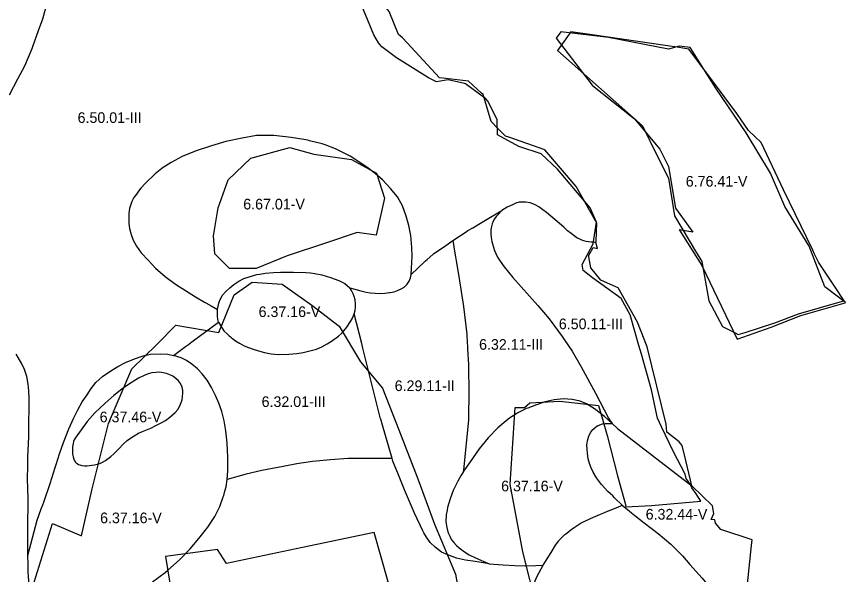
# Model space of a CAD drawing. Extents: x -555156 to -540209, y -1046851 to -1035695.
# Drawn here: x -542138 to -541359, y -1040907 to -1040382 of the extents above; entities that cross this region are included whole.
import ezdxf

# ---------------------------------------------------------------- set-up
doc = ezdxf.new("R2010")
doc.units = 0
for name, color, linetype in [('Vrstva 27', 7, 'Continuous'), ('Vrstva 28', 7, 'Continuous'), ('Vrstva 29', 7, 'Continuous')]:
    doc.layers.add(name, color=color, linetype=linetype)

msp = doc.modelspace()

# ---------------------------------------------------------------- linework, layer by layer
at = {"layer": 'Vrstva 28'}
for points in [[(-541593.76, -1040594.63), (-541593.48, -1040594.1), (-541593.07, -1040584.45), (-541592.73, -1040576.39), (-541600.47, -1040562.6), (-541602.39, -1040559.17), (-541612.08, -1040541.89), (-541641.71, -1040507.59), (-541675.45, -1040495.58), (-541678.57, -1040494.47), (-541685.72, -1040487.24), (-541692.18, -1040480.72), (-541699.7, -1040455.36), (-541701.04, -1040454.15), (-541713.43, -1040442.93), (-541734.8, -1040440.48), (-541740.52, -1040439.82), (-541770.98, -1040406.91), (-541775.35, -1040402.19), (-541779.11, -1040398.91), (-541788.04, -1040377.21), (-541798.74, -1040363.44)], [(-542144.84, -1040455.59), (-542137.07, -1040440.65), (-542130.51, -1040428.38), (-542123.64, -1040412.09), (-542122.95, -1040410.2), (-542117.51, -1040395.2), (-542113.48, -1040384.15), (-542109.84, -1040370.36)], [(-541453.1, -1040679.19), (-541425.36, -1040670.13), (-541403.1, -1040661.75), (-541361.89, -1040649.89), (-541360.03, -1040649.35), (-541369.26, -1040635.59), (-541384.41, -1040612.99), (-541387.93, -1040605.65), (-541389.7, -1040601.96), (-541417.07, -1040544.93), (-541438.36, -1040500.57), (-541450.27, -1040489.17), (-541460.97, -1040473.29), (-541495.79, -1040426.52), (-541506.12, -1040412.64), (-541509.91, -1040412.09), (-541517.03, -1040411.05), (-541526.16, -1040409.72), (-541597.19, -1040399.34), (-541617.11, -1040396.43), (-541629.8, -1040414.09), (-541549.65, -1040484.93), (-541535.57, -1040513.88), (-541525.44, -1040534.19), (-541519.72, -1040569.58)], [(-541766.63, -1040613.12), (-541766.57, -1040611.85), (-541766.45, -1040609.32), (-541766.48, -1040607.52), (-541766.6, -1040599.3), (-541767.49, -1040588.09), (-541769.44, -1040578.68), (-541771.98, -1040569.71), (-541775.56, -1040560.15), (-541780.19, -1040551.78), (-541786.61, -1040543.71), (-541794.08, -1040535.64), (-541801.25, -1040529.66), (-541808.87, -1040523.72), (-541824.7, -1040513.26), (-541838.29, -1040506.38), (-541848.26, -1040502.74), (-541850.99, -1040501.75), (-541862.76, -1040498.84), (-541864.28, -1040498.46), (-541868.25, -1040497.79), (-541880.12, -1040495.77), (-541896.25, -1040493.98), (-541912.68, -1040494.13), (-541926.12, -1040496.37), (-541941.66, -1040499.66), (-541955.1, -1040503.84), (-541969.44, -1040508.47), (-541982.73, -1040513.85), (-541992.89, -1040519.38), (-542001.26, -1040524.78), (-542001.7, -1040525.06), (-542007.98, -1040530.14), (-542017.09, -1040538.81), (-542021.33, -1040543.48), (-542023.55, -1040546.21), (-542025.6, -1040549.03), (-542027.99, -1040552.36), (-542029.86, -1040556.04), (-542031.23, -1040559.71), (-542032, -1040562.7), (-542032.77, -1040566.88), (-542032.77, -1040571.24), (-542032.59, -1040576.62), (-542032, -1040581.31), (-542030.55, -1040587.12), (-542028.75, -1040592.42), (-542025.43, -1040597.97), (-542021.09, -1040604.36), (-542014.69, -1040611.28), (-542007.52, -1040618.88), (-541998.65, -1040626.48), (-541988.74, -1040633.74), (-541969.91, -1040645.79), (-541961.55, -1040650.87), (-541960.42, -1040651.5), (-541955.36, -1040654.31), (-541949.45, -1040657.6)], [(-541593.76, -1040594.63), (-541594.82, -1040594.55), (-541596.25, -1040594.44), (-541598.14, -1040594.22), (-541600.76, -1040593.88), (-541602.63, -1040593.55), (-541604.78, -1040592.99), (-541606.78, -1040592.35), (-541608.79, -1040591.51), (-541610.86, -1040590.55), (-541612.59, -1040589.49), (-541614.48, -1040588.13), (-541616.97, -1040586.13), (-541620.19, -1040583.5), (-541623.75, -1040580.32), (-541631.88, -1040573.31), (-541640.05, -1040566.5), (-541643.55, -1040563.77), (-541647.14, -1040561.2), (-541650.55, -1040559.32), (-541653.03, -1040558.21), (-541655.5, -1040557.36), (-541659.34, -1040556.68), (-541662.67, -1040556.59), (-541665.83, -1040556.76), (-541668.82, -1040557.62), (-541672.15, -1040559.07), (-541677.03, -1040561.48), (-541682.16, -1040564.5)], [(-541728.16, -1040592.75), (-541715.69, -1040584.6), (-541713.97, -1040583.48), (-541709.32, -1040580.69), (-541700.53, -1040575.41), (-541690.97, -1040569.73), (-541682.16, -1040564.5)], [(-541682.16, -1040564.5), (-541685.9, -1040568.45), (-541687.51, -1040570.26), (-541688.92, -1040572.31), (-541690.24, -1040574.5), (-541691.26, -1040576.99), (-541691.9, -1040579.43), (-541692.29, -1040582.8), (-541692.29, -1040586.36), (-541692.09, -1040589.83), (-541691.46, -1040593.53), (-541689.14, -1040601.35), (-541688.83, -1040602.05), (-541687.57, -1040604.88), (-541686.01, -1040608.38), (-541683.47, -1040612.07), (-541679.73, -1040617.5), (-541671.82, -1040627.51), (-541648.09, -1040653.81), (-541637.38, -1040666.37), (-541628.67, -1040678.22), (-541627.97, -1040679.18), (-541626.05, -1040681.98), (-541623.49, -1040685.7), (-541615.94, -1040696.7), (-541607.58, -1040711.61), (-541593.99, -1040736.46)], [(-541519.72, -1040569.58), (-541498.86, -1040604.18), (-541496.75, -1040607.69), (-541493.95, -1040612.33), (-541487.3, -1040649.38), (-541474.46, -1040673.56), (-541462.77, -1040679.71), (-541459.84, -1040681.25), (-541453.1, -1040679.19)], [(-541767.2, -1040624.86), (-541754.75, -1040612.75), (-541753.86, -1040611.88), (-541752.24, -1040610.48), (-541746.99, -1040605.91), (-541745.94, -1040605), (-541736.83, -1040599.02), (-541728.16, -1040592.75)], [(-541728.16, -1040592.75), (-541726.15, -1040604.58), (-541725.56, -1040608.08), (-541724.92, -1040611.82), (-541722.39, -1040626.7)], [(-541503.49, -1040823.59), (-541504.79, -1040818.07), (-541509.15, -1040799.56), (-541512.44, -1040785.61), (-541513.95, -1040783.61), (-541515.19, -1040781.97), (-541527.02, -1040773.11), (-541527.61, -1040765.52), (-541545.26, -1040692.82), (-541546.61, -1040689.46), (-541548.24, -1040685.4), (-541554.63, -1040669.51), (-541572.61, -1040637.27), (-541574.2, -1040636.57), (-541588.99, -1040630.06), (-541598.3, -1040618.46), (-541600.29, -1040608.13), (-541600.45, -1040607.31), (-541596.27, -1040599.38), (-541592.01, -1040600.3), (-541593.76, -1040594.63)], [(-541767.2, -1040624.86), (-541766.63, -1040613.12)], [(-541949.45, -1040657.6), (-541948.24, -1040651.73), (-541947.9, -1040650.84), (-541946.87, -1040648.14), (-541945.41, -1040645.51), (-541944.83, -1040644.47), (-541941.67, -1040640.62), (-541937.91, -1040637.12), (-541933.9, -1040634.05), (-541929.21, -1040630.89), (-541924.68, -1040628.5), (-541919.73, -1040626.79), (-541912.31, -1040624.74), (-541909.49, -1040624.3), (-541904.62, -1040623.54), (-541896.69, -1040622.78), (-541890.2, -1040622.62), (-541886.44, -1040622.52), (-541878, -1040622.43), (-541877.82, -1040622.43), (-541866.21, -1040622.69), (-541861.9, -1040623.21), (-541857.76, -1040623.71), (-541851.19, -1040624.91), (-541843, -1040627.39), (-541835.15, -1040630.46), (-541829.78, -1040633.27), (-541827.05, -1040635.27), (-541825, -1040637.13)], [(-541825, -1040637.13), (-541820.27, -1040638.56), (-541814.55, -1040640.18), (-541809.6, -1040641.29), (-541805.59, -1040641.98), (-541801.24, -1040642.4), (-541796.46, -1040642.58), (-541792.1, -1040642.4), (-541787.57, -1040641.79), (-541787.07, -1040641.72), (-541783.23, -1040640.87), (-541779.98, -1040639.67), (-541776.83, -1040638.31), (-541773.75, -1040636.51), (-541771.11, -1040633.69), (-541769.77, -1040631.81), (-541769.23, -1040631.05), (-541768.03, -1040627.8), (-541767.2, -1040624.86)], [(-541722.39, -1040626.7), (-541717.94, -1040654.68), (-541715.07, -1040680.84), (-541714.63, -1040688.92), (-541714.45, -1040692.15), (-541714.29, -1040695.02), (-541713.5, -1040709.35), (-541712.98, -1040737.59), (-541713.41, -1040757.44), (-541713.5, -1040761.65), (-541718.21, -1040808.41), (-541718.44, -1040810.69)], [(-541820.72, -1040661.8), (-541820.04, -1040658.72), (-541819.65, -1040655.4), (-541819.5, -1040652.28), (-541819.88, -1040648.65), (-541820.71, -1040645.52), (-541821.73, -1040642.74), (-541823.25, -1040639.81), (-541825, -1040637.13)], [(-541948.34, -1040669.66), (-541948.98, -1040667.13), (-541949.37, -1040663.81), (-541949.46, -1040660), (-541949.45, -1040657.6)], [(-541882.19, -1040699.74), (-541874.76, -1040698.97), (-541868.7, -1040698.03), (-541862.56, -1040696.49), (-541856.41, -1040694.87), (-541851.12, -1040692.65), (-541846.25, -1040690), (-541843.68, -1040688.32), (-541841.37, -1040686.81), (-541839.85, -1040685.82), (-541835.58, -1040682.57), (-541832.26, -1040679.5), (-541827.82, -1040674.29), (-541824.38, -1040669.07), (-541822.43, -1040665.65), (-541820.72, -1040661.8)], [(-541812.67, -1040693.87), (-541813.38, -1040691.02), (-541814.07, -1040688.27), (-541820.72, -1040661.8)], [(-541990.68, -1040700.75), (-541979.31, -1040692.4), (-541976.74, -1040690.51), (-541973.51, -1040688.14), (-541948.34, -1040669.66)], [(-541948.34, -1040669.66), (-541946.68, -1040672.59), (-541945.07, -1040675.23), (-541943.26, -1040677.73), (-541940.1, -1040680.8), (-541938.76, -1040681.94), (-541937.02, -1040683.41), (-541936.17, -1040684.13), (-541935.28, -1040684.8), (-541932.42, -1040686.95), (-541928.66, -1040689.43), (-541924.14, -1040691.65), (-541920.21, -1040693.36), (-541915.77, -1040694.98), (-541910.91, -1040696.6), (-541905.11, -1040698.14), (-541898.96, -1040699.33), (-541891.88, -1040699.85), (-541882.19, -1040699.74)], [(-542127.79, -1040889.01), (-542127.64, -1040859.67), (-542127.38, -1040840.58), (-542127.39, -1040839.99), (-542127.49, -1040835.62), (-542127.9, -1040816.51), (-542127.75, -1040805.18), (-542127.64, -1040796.64), (-542126.85, -1040777.28), (-542126.59, -1040758.93), (-542126.55, -1040755.77), (-542126.51, -1040753.28), (-542126.49, -1040751.78), (-542126.49, -1040741.32), (-542126.64, -1040734.15), (-542127.39, -1040727.72), (-542128.73, -1040720.7), (-542130.82, -1040714.12), (-542133.66, -1040708), (-542138.74, -1040699.7)], [(-542127.79, -1040889.01), (-542119.02, -1040855.8), (-542115.09, -1040845.12), (-542113.68, -1040841.28), (-542112.75, -1040838.77), (-542106.62, -1040821.43), (-542101.99, -1040806.34), (-542101.04, -1040803.4), (-542097.81, -1040793.33), (-542094.08, -1040782.72), (-542089.18, -1040769.87), (-542084.55, -1040759.41), (-542080.52, -1040752.09), (-542076.49, -1040744.61), (-542072.01, -1040737.74), (-542068.12, -1040731.91), (-542063.64, -1040726.38), (-542057.52, -1040720.7), (-542049.6, -1040715.17), (-542043.03, -1040711.14), (-542035.71, -1040707.55), (-542027.35, -1040703.96), (-542019.13, -1040701.27), (-542012.41, -1040699.78), (-542002.77, -1040699.4), (-541996.05, -1040699.7), (-541990.68, -1040700.75)], [(-541785.2, -1040797.87), (-541788.65, -1040786), (-541794.22, -1040766.55), (-541795.85, -1040760.86), (-541795.95, -1040760.45), (-541812.67, -1040693.87)], [(-541968.12, -1040713.45), (-541973.5, -1040708.97), (-541978.58, -1040705.53), (-541983.65, -1040703.14), (-541990.68, -1040700.75)], [(-541940.24, -1040817.54), (-541939.59, -1040809.4), (-541939.74, -1040796.55), (-541940.19, -1040783.4), (-541941.12, -1040774.42), (-541941.38, -1040771.89), (-541943.03, -1040762.32), (-541945.42, -1040753.51), (-541947.96, -1040745.88), (-541951.39, -1040738.56), (-541954.98, -1040731.09), (-541959.16, -1040724.21), (-541963.79, -1040718.24), (-541968.12, -1040713.45)], [(-542071.87, -1040804.56), (-542069.67, -1040804.47), (-542067.43, -1040804.17), (-542064.99, -1040803.73), (-542062.36, -1040803.2), (-542060.07, -1040802.37), (-542057.48, -1040801.15), (-542054.7, -1040799.59), (-542052.11, -1040797.83), (-542049.58, -1040795.93), (-542046.79, -1040793.52), (-542042.26, -1040788.82), (-542038.17, -1040784.38), (-542034.15, -1040780.79), (-542031, -1040778.49), (-542027.84, -1040776.44), (-542023.66, -1040774.05), (-542019.99, -1040772.25), (-542016.7, -1040770.97), (-542012.18, -1040769.09), (-542007.31, -1040766.79), (-542002.19, -1040764.31), (-541998.35, -1040762.01), (-541994.17, -1040759.02), (-541989.14, -1040754.51), (-541986.8, -1040751.58), (-541984.8, -1040748.24), (-541983.52, -1040744.99), (-541982.67, -1040742.6), (-541982.16, -1040739.53), (-541981.9, -1040736.28), (-541981.9, -1040733.97), (-541982.67, -1040730.56), (-541984.29, -1040727.31), (-541986.17, -1040724.75), (-541988.65, -1040722.45), (-541991.46, -1040720.48), (-541994.28, -1040718.94), (-541997.35, -1040717.83), (-542000.51, -1040717.07), (-542003.58, -1040716.72), (-542007.17, -1040716.81), (-542011.01, -1040717.32), (-542014.42, -1040718.18), (-542018.26, -1040719.63), (-542023.49, -1040722.32), (-542032.15, -1040727.7), (-542039.32, -1040732.63), (-542046.94, -1040738.61), (-542055.31, -1040745.93), (-542064.57, -1040754.75), (-542071.89, -1040762.97), (-542083.24, -1040778.66), (-542084.08, -1040780.33), (-542084.62, -1040781.85), (-542085.16, -1040783.8), (-542085.64, -1040786.87), (-542085.74, -1040789.21), (-542085.69, -1040791.56), (-542085.64, -1040793.7), (-542085.06, -1040796.19), (-542084.35, -1040798.51), (-542083.67, -1040799.93), (-542082.74, -1040801.29), (-542082.25, -1040801.74), (-542081.43, -1040802.51), (-542079.96, -1040803.29), (-542078.75, -1040803.83), (-542076.89, -1040804.27)], [(-541593.99, -1040736.46), (-541581.83, -1040759.93), (-541580.69, -1040761.46), (-541578.21, -1040764.79)], [(-541578.21, -1040764.79), (-541581.96, -1040761.34), (-541585.41, -1040758.16), (-541594.97, -1040750.99), (-541602.44, -1040746.36), (-541608.27, -1040743.82), (-541616.03, -1040742.17), (-541623.95, -1040741.72), (-541632.76, -1040742.47), (-541641.28, -1040744.56), (-541649.39, -1040747.22), (-541649.49, -1040747.25), (-541657.61, -1040750.3), (-541659.05, -1040750.84), (-541661.93, -1040752.31), (-541666.97, -1040754.88), (-541667.94, -1040755.51), (-541674.67, -1040759.88), (-541675.93, -1040760.7), (-541685.64, -1040768.92), (-541694.75, -1040778.34), (-541703.26, -1040788.8), (-541711.87, -1040800.82), (-541717.02, -1040808.56), (-541718.44, -1040810.69)], [(-541568.84, -1040841.7), (-541576.01, -1040834.67), (-541577.75, -1040833.02), (-541582.28, -1040828.7), (-541588.26, -1040822.12), (-541593.18, -1040815.99), (-541596.27, -1040810.58), (-541598.15, -1040806.4), (-541599.6, -1040802.39), (-541600.79, -1040798.12), (-541601.47, -1040792.91), (-541601.82, -1040788.89), (-541601.99, -1040784.96), (-541601.56, -1040781.04), (-541600.62, -1040777.62), (-541599.68, -1040775.14), (-541598.32, -1040772.92), (-541596.52, -1040770.62), (-541594.73, -1040768.82), (-541592.34, -1040767.2), (-541591.73, -1040766.91), (-541589.87, -1040766.01), (-541587.48, -1040765.32), (-541584.75, -1040764.98), (-541582.01, -1040764.81), (-541578.21, -1040764.79)], [(-541578.21, -1040764.79), (-541573.13, -1040769.57), (-541503.49, -1040823.59)], [(-541785.2, -1040797.87), (-541798.61, -1040797.77), (-541812.5, -1040797.77), (-541826.39, -1040797.92), (-541842.97, -1040798.97), (-541860, -1040800.61), (-541874.79, -1040802.85), (-541887.63, -1040805.39), (-541907.65, -1040809.13), (-541922.28, -1040812.42), (-541940.24, -1040817.54)], [(-541694.03, -1040896.81), (-541707.18, -1040894.72), (-541716.14, -1040893.37), (-541724.65, -1040891.43), (-541732.72, -1040888.44), (-541738.69, -1040885.75), (-541744.67, -1040881.27), (-541749.45, -1040876.63), (-541752.74, -1040871.85), (-541755.28, -1040867.71), (-541756.43, -1040865.83), (-541764.27, -1040849.1), (-541773.68, -1040827.13), (-541779.93, -1040811.6), (-541782.3, -1040805.73), (-541784.53, -1040800.19), (-541785.2, -1040797.87)], [(-542076.89, -1040804.27), (-542074.5, -1040804.56), (-542071.87, -1040804.56)], [(-541718.44, -1040810.69), (-541720.17, -1040813.58), (-541723.52, -1040819.2), (-541727.71, -1040827.72), (-541730.69, -1040835.79), (-541733.08, -1040844.01), (-541733.47, -1040846.27), (-541734.28, -1040850.89), (-541734.54, -1040857.45), (-541733.86, -1040862.66), (-541732.67, -1040866.84), (-541732.07, -1040868.21), (-541730.87, -1040870.94), (-541729.25, -1040874.19), (-541727.29, -1040876.83), (-541724.64, -1040879.57), (-541722.04, -1040881.87), (-541717.26, -1040885.61), (-541712.78, -1040888.3), (-541706.8, -1040891.29), (-541694.03, -1040896.81)], [(-542010.55, -1040913.79), (-541998.45, -1040904.97), (-541995.92, -1040902.74), (-541985.01, -1040893.17), (-541975, -1040882.85), (-541966.82, -1040873.14), (-541958.31, -1040862.23), (-541951.89, -1040852.22), (-541947.26, -1040842.95), (-541943.93, -1040833.78), (-541943.52, -1040832.64), (-541942.43, -1040828.64), (-541941.28, -1040824.42), (-541940.24, -1040817.54)], [(-541451.53, -1040937.71), (-541452.1, -1040933.94), (-541452.57, -1040930.82), (-541447.15, -1040879.66), (-541446.57, -1040874.15), (-541476.12, -1040864.59), (-541481.08, -1040858.73), (-541481.64, -1040855.4), (-541482.26, -1040855.37), (-541485.3, -1040855.23), (-541482.64, -1040849.4), (-541483.84, -1040842.23), (-541503.49, -1040823.59)], [(-541643.25, -1040898.15), (-541635.73, -1040886.28), (-541631.7, -1040879.41), (-541628.42, -1040875.2), (-541627.97, -1040874.62), (-541624.85, -1040871.41), (-541622.74, -1040869.24), (-541621.89, -1040868.57), (-541615.87, -1040863.86), (-541607.35, -1040858.33), (-541595.85, -1040852.8), (-541589.31, -1040850.16), (-541586.28, -1040848.94), (-541582.54, -1040847.42), (-541581.81, -1040847.13), (-541572.95, -1040843.42), (-541568.84, -1040841.7)], [(-541568.84, -1040841.7), (-541562.46, -1040846.98), (-541560.17, -1040848.87), (-541557.04, -1040851.31), (-541548.08, -1040858.29), (-541535.08, -1040868.45), (-541523.28, -1040878.31), (-541520.69, -1040880.83), (-541512.08, -1040889.22), (-541505.13, -1040897.44), (-541493.63, -1040910.44), (-541479.44, -1040927.18), (-541475.39, -1040932.07), (-541472.3, -1040935.8), (-541463.64, -1040946.24), (-541454.38, -1040956.55), (-541447.73, -1040962.91)], [(-542113.35, -1040938.19), (-542117.02, -1040935.55), (-542119.58, -1040932.81), (-542122.48, -1040928.71), (-542124.27, -1040924.87), (-542125.49, -1040919.68), (-542125.55, -1040919.41), (-542125.78, -1040918.23), (-542126.75, -1040913.26), (-542127.13, -1040908.46), (-542127.43, -1040904.63), (-542127.52, -1040897.2), (-542127.79, -1040889.01)], [(-541694.03, -1040896.81), (-541680.89, -1040897.85), (-541669.84, -1040898.45)], [(-541669.84, -1040898.45), (-541659.98, -1040898.6), (-541650.12, -1040898.45)], [(-541664.64, -1040982.82), (-541664.47, -1040980.04), (-541664.34, -1040977.87), (-541664.12, -1040973.16), (-541662.76, -1040962.45), (-541659.19, -1040944.36), (-541657.55, -1040935.69), (-541655.16, -1040925.83), (-541652.47, -1040917.16), (-541648.73, -1040908.49), (-541643.25, -1040898.15)], [(-541650.12, -1040898.45), (-541643.25, -1040898.15)]]:
    msp.add_lwpolyline(points, dxfattribs=at)
at = {"layer": 'Vrstva 29'}
for points in [[(-541499.337731, -1040830.86074), (-541503.54, -1040825.26), (-541505.042599, -1040821.986787), (-541508.577002, -1040816.489003), (-541509.558251, -1040812.352746), (-541520.48, -1040791.52), (-541531.78, -1040767.89), (-541535.69, -1040759.72), (-541536.27, -1040757), (-541541.37, -1040733.07), (-541550.85, -1040699.61), (-541553.1, -1040691.61), (-541561.22, -1040662.68), (-541569.87, -1040647.16), (-541596.85, -1040627.87), (-541605.45, -1040621.1), (-541606.43, -1040615.26), (-541596.08, -1040596.02), (-541592.89, -1040575.35), (-541598.97, -1040562.07), (-541629.69, -1040525.49), (-541644.9, -1040511.11), (-541666.19, -1040504.35), (-541686.26, -1040493.3), (-541686.38, -1040479.21), (-541694.99, -1040462.08), (-541697.145784, -1040459.480462), (-541716.068425, -1040445.529714), (-541717.09, -1040445.22), (-541732.4, -1040441.6), (-541743.39, -1040443.61), (-541751.04, -1040439.87), (-541780.92, -1040420.98), (-541794.92, -1040410.66), (-541797.92, -1040406.91), (-541802.32, -1040399.16), (-541818.1, -1040361.05)], [(-541515.189364, -1040409.87659), (-541525.44, -1040412.68), (-541581.825573, -1040401.800685), (-541626.490879, -1040396.38752), (-541631.020263, -1040402.345961), (-541597.206148, -1040446.570215), (-541596.87, -1040446.95), (-541557.2, -1040478.44), (-541533.56, -1040506.69), (-541525.25, -1040523.23), (-541518.648586, -1040562.180297), (-541502.402998, -1040584.755998), (-541515.15517, -1040582.792486), (-541515.12, -1040583), (-541494.04, -1040616.21), (-541460.71, -1040685.48), (-541428.95, -1040674.29), (-541400.94, -1040663.23), (-541359.21, -1040651.26), (-541358.988502, -1040650.969432), (-541378.438997, -1040636.274003), (-541393.146992, -1040598.040998), (-541416.103998, -1040560.79), (-541429.536, -1040529.532003), (-541452.402993, -1040491.524004), (-541480.938002, -1040449.517006), (-541505.037003, -1040411.106995), (-541515.189364, -1040409.87659)], [(-541799.715993, -1040529.340999), (-541792.312007, -1040552.881002), (-541800.211998, -1040587.781996), (-541818.071995, -1040585.071), (-541847.023991, -1040594.945007), (-541883.915008, -1040607.275001), (-541913.059998, -1040618.915997), (-541938.129993, -1040618.996009), (-541951.971006, -1040605.226995), (-541953.212998, -1040588.487996), (-541948.805005, -1040562.147), (-541939.259003, -1040535.598993), (-541917.881, -1040515.449002), (-541881.462006, -1040505.111001), (-541858.878002, -1040511.402003), (-541823.382001, -1040516.545999), (-541799.715993, -1040529.340999)], [(-542121.732003, -1040914.210991), (-542104.442995, -1040858.875009), (-542077.073999, -1040870.540999), (-542067.116995, -1040826.156995), (-542051.973005, -1040764.713004), (-542030.013994, -1040713.462995), (-542006.564004, -1040690.727993), (-541988.438995, -1040672.267003), (-541948.025993, -1040679.223003), (-541933.670004, -1040643.748), (-541916.767002, -1040631.795005), (-541888.604, -1040633.841004), (-541860.573008, -1040653.496998), (-541834.844001, -1040673.158997), (-541815.008993, -1040706.992998), (-541794.154991, -1040731.488008), (-541778.744994, -1040770.716006), (-541761.018001, -1040816.838006), (-541745.486991, -1040859.654997), (-541725.541009, -1040906.529007), (-541716.222001, -1040959.398007)], [(-541648.775008, -1040938.901002), (-541662.136999, -1040885.591991), (-541674.118009, -1040821.959992), (-541669.552995, -1040749.657001), (-541660.574506, -1040749.848351), (-541655.56, -1040745.31), (-541627.61, -1040743.82), (-541591.01, -1040747.98), (-541587.28, -1040760.83), (-541582.86, -1040776.04), (-541573.16, -1040814.04), (-541565.84, -1040840.91), (-541565.482588, -1040843.239269), (-541541.286008, -1040842.047009), (-541494.803991, -1040837.912998), (-541499.337731, -1040830.86074)], [(-541788.973022, -1040913.669983), (-541802.067993, -1040867.286011), (-541869.585022, -1040881.388977), (-541940.776978, -1040896.369995), (-541949.338989, -1040883.432007), (-541998.369995, -1040889.841003), (-541988.872009, -1040948.093994), (-541920.026978, -1040938.223022), (-541788.973022, -1040913.669983)]]:
    msp.add_lwpolyline(points, dxfattribs=at)

# ---------------------------------------------------------------- texts
at = {"layer": 'Vrstva 27'}
for s, p in [('6.50.01-III', (-542080.876548, -1040482.16)), ('6.76.41-V', (-541509.091006, -1040542.05)), ('6.67.01-V', (-541925.141006, -1040563.53)), ('6.37.16-V', (-541910.697974, -1040664.71)), ('6.50.11-III', (-541628.426548, -1040676.18)), ('6.32.11-III', (-541703.436548, -1040695.48)), ('6.29.11-II', (-541782.760313, -1040734.34)), ('6.32.01-III', (-541907.886548, -1040749.31)), ('6.37.46-V', (-542060.137974, -1040763.71)), ('6.37.16-V', (-541682.657974, -1040828.63)), ('6.32.44-V', (-541546.770884, -1040855.19)), ('6.37.16-V', (-542059.737974, -1040858.63))]:
    msp.add_text(s, height=10, dxfattribs=at).set_placement(p)

doc.saveas('drawing.dxf')
